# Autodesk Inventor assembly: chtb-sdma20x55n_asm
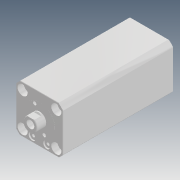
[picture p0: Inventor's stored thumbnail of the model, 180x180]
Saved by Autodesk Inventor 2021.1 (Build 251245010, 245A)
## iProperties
Created: 2018-05
Part Number: chtb-sdma20x55n_asm
Description: STEP AP214
Document SubType Name: Assembly
Designer: user
Title: chtb-sdma20x55n_asm.STEP
Revision Number: ÈÎºÎ
Sending System: SolidWorks 2016
Preprocessor: SwSTEP 2.0
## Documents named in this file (5)
- D:\Vault_2016\Projekty\Clamptek\Hydraulic\CHTB\CHTB-20\Inventor\CHTB-SDMA20x55N\chtb-sdma20x55n_asm.iam
- D:\Vault_2016\Projekty\Clamptek\Hydraulic\CHTB\CHTB-20\Inventor\CHTB-SDMA20x55N\CHTB-SDMA20X55NBT.ipt
- D:\Vault_2016\Projekty\Clamptek\Hydraulic\CHTB\CHTB-20\Inventor\CHTB-SDMA20x55N\CHTB-SDMA20X55NHSG.ipt
- D:\Vault_2016\Projekty\Clamptek\Hydraulic\CHTB\CHTB-20\Inventor\CHTB-SDMA20x55N\QG_3.ipt
- D:\Vault_2016\Projekty\Clamptek\Hydraulic\CHTB\CHTB-20\Inventor\CHTB-SDMA20x55N\socket set screw flat point_iso_ISO 4026 - M5 x 5-N.ipt
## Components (5 placed, 5 different names)
1. CHTB-SDMA20X55NBT_1
2. CHTB-SDMA20X55NHSG_2
3. QG_3_3
4. socket set screw flat point_iso_ISO 4026 - M5 x 5-N_4
5. socket set screw flat point_iso_ISO 4026 - M5 x 5-N_5
